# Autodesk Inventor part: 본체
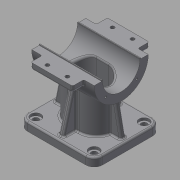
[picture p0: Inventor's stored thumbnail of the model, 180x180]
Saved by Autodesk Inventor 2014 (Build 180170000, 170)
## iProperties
Created: 2015-12
Part Number: 본체
Material: 알루미늄 6061
Document SubType Name: Modeling
Designer: mduedu
Density: 1 g/cm^3
Appearance: 알루미늄 - 평지
Author: mduedu
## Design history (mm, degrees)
sketch "스케치1"
  geometry: L1 (45, 40)-(-45, 40); L2 (-45, 40)-(-45, -40); L3 (-45, -40)-(45, -40); L4 (45, -40)-(45, 40); L5 (45, 40)-(-45, -40); L6 (-45, 40)-(45, -40); 1 further point
  constraints: 12 end point, 2 midpoint, 2 parallel, 1 horizontal, 1 perpendicular
  dimensions: "d0" = 90 distance of L2.end L3.end; "d2" = 80 distance of L1.end L2.end
extrude "돌출1" new body sketch "스케치1" distance "d3" = 10; taper "d4" = 0 deg
sketch "스케치2"
  geometry: L1 (0, 40)-(0, -40) reference; C1 r 32.5 at (80, 0); 1 further point
  constraints: 1 centre point
  dimensions: "d5" = 65 diameter of C1; "d6" = 80 distance from line of C1.centre L1
extrude "돌출2" join sketch "스케치2" stored distance "d7" = 75; taper "d8" = 0 deg
sketch "스케치3"
  geometry: L1 (-27.5, -20)-(27.5, -20); L2 (27.5, -20)-(27.5, 20); L3 (27.5, 20)-(-27.5, 20); L4 (-27.5, 20)-(-27.5, -20); L5 (-27.5, -20)-(27.5, 20); L6 (27.5, -20)-(-27.5, 20); 1 further point
  constraints: 12 end point, 2 midpoint, 2 parallel, 1 horizontal, 1 perpendicular
  dimensions: "d9" = 55 distance of L2.end L3.end; "d11" = 40 distance of L1.end L2.end
extrude "돌출3" new body sketch "스케치3" stored distance "d12" = 75; taper "d13" = 0 deg
fillet "모깎기1"
fillet "모깎기2"
feature "결합1"
  node "솔리드2"
fillet "모깎기3" dims "d14" = 10
sketch "스케치4"
  geometry: L1 (-37.5, 47.5)-(37.5, 47.5) reference; L2 (35, 10)-(45, 10) reference; L3 (32.5, 47.5)-(40, 10); L4 (37.5, 47.5)-(37.5, 112.5) reference; L5 (45, 10)-(45, 0) reference; 1 further point
  constraints: 2 end point, 1 midpoint, 1 point on line
  dimensions: "d15" = 5 distance from line of L3.start L4; "d16" = 5 distance from line of L3.end L5
sketch "스케치5"
  geometry: L1 (10, 40)-(10, 30) reference; L2 (10, 35)-(56.569, 22.522); L3 (0, 40)-(10, 40) reference; 2 further points
  constraints: 2 end point, 1 midpoint, 2 other
  dimensions: "d17" = 5 distance from line of L2.start L3; "d18" = 15 deg angle of L2 L3
feature "리브1" dims "d19" = 1, "d20" = 6, "d21" = 0, "d22" = 0, "d23" = 1, "d24" = 1
feature "리브2" dims "d25" = 1, "d26" = 6, "d27" = 0, "d28" = 0, "d29" = 1, "d30" = 1
fillet "모깎기4" dims "d31" = 2
fillet "모깎기5" dims "d32" = 2
fillet "모깎기6" dims "d33" = 2
sketch "스케치6"
  geometry: A1 r 10 centre (-35, 30) between (-35, 40) and (-45, 30) reference; A2 r 10 centre (35, 30) between (45, 30) and (35, 40) reference; A3 r 10 centre (35, -30) between (35, -40) and (45, -30) reference; A4 r 10 centre (-35, -30) between (-45, -30) and (-35, -40) reference; 5 further points
  constraints: 4 coincident
hole "구멍1" sketch "스케치6" at (-35, 30), (35, 30), (35, -30), (-35, -30) diameter "d34" = 7; stored, may be unused: countersink angle "d38" = 90 deg, drill point angle "d40" = 118 deg; dims "d35" = 6, "d36" = 12, "d37" = 3, "d39" = 8
fillet "모깎기7" dims "d41" = 2
hole "구멍2" diameter "d44" = 45; stored, may be unused: countersink angle "d48" = 90 deg, drill point angle "d50" = 118 deg; dims "d42" = 10, "d43" = 10, "d45" = 6, "d46" = 4, "d47" = 2, "d49" = 8
sketch "스케치7" dims "d52" = 26.5
  geometry: L1 (0, 0)-(32.5, 0); L2 (0, 0)-(22.981, 22.981); A1 r 32.5 centre (0, 0) between (32.5, 0) and (22.981, 22.981) reference; 3 further points
  constraints: 4 end point, 2 point on circle, 1 coincident, 1 horizontal, 1 point on line, 3 other
  dimensions: "d51" = 45 deg angle of L2 L1
hole "구멍3" sketch "스케치7" at (18.738, 18.738) diameter "d54" = 2.459; stored, may be unused: countersink angle "d58" = 90 deg, drill point angle "d60" = 118 deg; dims "d55" = 8, "d56" = 4, "d57" = 2, "d59" = 10
sketch "스케치8"
  geometry: L1 (72.5, 31.623)-(72.5, 46); L2 (72.5, 46)-(87.5, 46); L3 (87.5, 46)-(87.5, 31.623); A1 r 32.5 centre (80, 0) between (87.5, 31.623) and (72.5, 31.623) reference; 2 further points
  constraints: 6 end point, 2 point on circle, 1 midpoint, 1 parallel, 1 vertical, 1 vertical alignment
  dimensions: "d64" = 15 distance of L1.end L2.end; "d66" = 46 distance from line of L2 A1.centre
extrude "돌출4" join sketch "스케치8" stored distance "d67" = 50; taper "d68" = 0 deg
fillet "모깎기8" dims "d69" = 3
fillet "모깎기9" dims "d70" = 2
sketch "스케치9"
  geometry: L1 (-76, 82.5)-(76, 82.5); L2 (76, 82.5)-(76, 0); L3 (76, 0)-(-76, 0); L4 (-76, 0)-(-76, 82.5); L5 (-46, 4.5)-(-46, -4.5) reference; C1 r 32.5 at (0, 0) reference; 2 further points
  constraints: 8 end point, 2 parallel, 1 coincident, 1 horizontal, 1 midpoint, 1 perpendicular
  dimensions: "d71" = 50 distance edge to line of C1 L1; "d72" = 30 distance between parallel lines of L4 L5
extrude "돌출5" cut sketch "스케치9" stored distance "d73" = 0; taper "d74" = 0 deg
node "작업 평면1"
sketch "스케치10"
  geometry: L1 (-7.5, 15)-(7.5, 15); L2 (-7.5, -15)-(7.5, -15); A1 r 20 centre (-7.5, 0) between (-7.5, 20) and (-26.977, 4.545) reference; A2 r 20 centre (7.5, 0) between (26.977, 4.545) and (7.5, 20) reference; A3 r 15 centre (-7.5, 0) between (-7.5, 15) and (-7.5, -15); A4 r 15 centre (7.5, 0) between (7.5, -15) and (7.5, 15); 1 further point
  constraints: 7 point on circle, 4 end point, 4 tangent, 3 point on line, 2 centre point, 2 coincident, 1 horizontal
  dimensions: "d77" = 5 radial gap between concentric circles of A3 A1
extrude "돌출6" cut sketch "스케치10" stored distance "d78" = 50; taper "d79" = 0 deg
fillet "모깎기10" dims "d80" = 3
sketch "스케치11"
  geometry: 2 further points
  constraints: 1 coincident
hole "구멍4" sketch "스케치11" at (0, 0) diameter "d81" = 12; stored, may be unused: countersink angle "d85" = 90 deg, drill point angle "d87" = 118 deg; dims "d82" = 8, "d83" = 40, "d84" = 10, "d86" = 10
sketch "스케치12"
  geometry: C1 r 10 at (0, 0); 1 further point
  constraints: 1 centre point, 1 coincident
  dimensions: "d88" = 20 diameter of C1
extrude "돌출7" cut sketch "스케치12" distance "d89" = 5; taper "d90" = 0 deg
chamfer "모따기1" distance "d91" = 1; stored, may be unused: second distance "d92" = 2, angle "d93" = 45 deg
fillet "모깎기11" dims "d94" = 0.5
feature "립1" dims "d95" = 1, "d96" = 1, "d97" = 0, "d98" = 3 deg, "d99" = 3 deg, "d100" = 0
sketch "스케치13"
  geometry: 4 further points
hole "구멍5" sketch "스케치13" at (34, 5.936), (10, -72.269), (34, -72.269), (10, 5.936) diameter "d101" = 4.5; stored, may be unused: countersink angle "d105" = 90 deg, drill point angle "d107" = 0 deg; dims "d102" = 6, "d103" = 4, "d104" = 2, "d106" = 8
fillet "모깎기12" dims "d115" = 0.3
node "솔리드1"
mirror "대칭1"
mirror "대칭2"
pattern_circular "원형 패턴1" dims angle "d62" = 360 deg
mirror "대칭3"
mirror "대칭4"
